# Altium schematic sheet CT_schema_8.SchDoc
size 278 x 170 mm
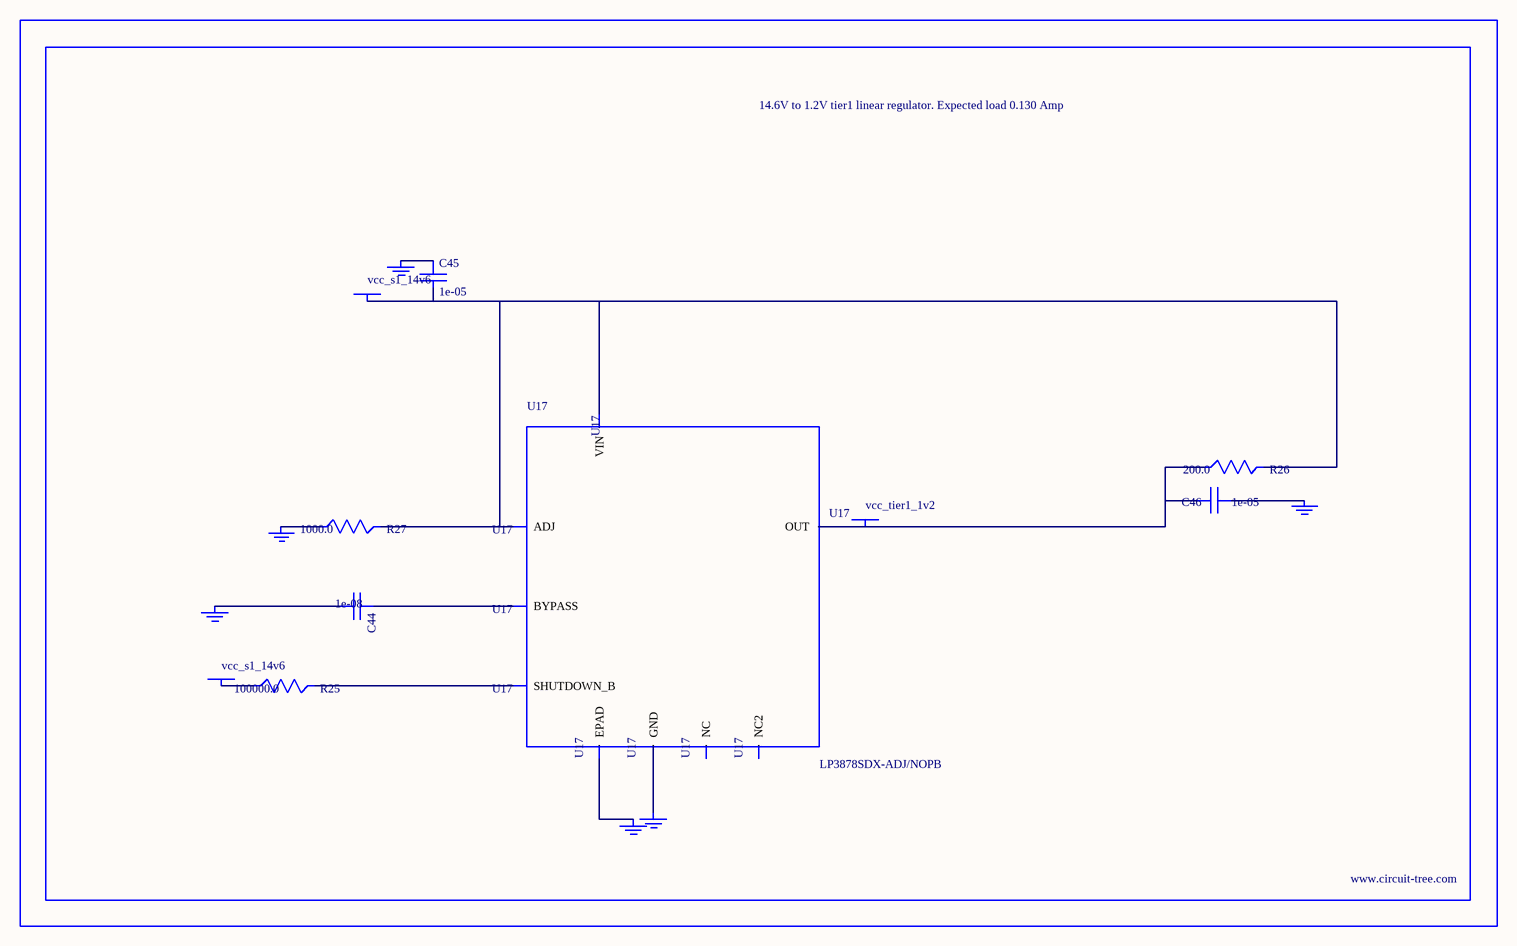
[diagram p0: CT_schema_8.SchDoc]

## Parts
BORDER7  (no value)
C44  1e-08  [C0402]
C45  1e-05  [C1210]
C46  1e-05  [C0805]
GND_INSTANCE_7_0  (no value)
GND_INSTANCE_7_1  (no value)
GND_INSTANCE_7_2  (no value)
GND_INSTANCE_7_3  (no value)
GND_INSTANCE_7_4  (no value)
GND_INSTANCE_7_5  (no value)
POWER_INSTANCE_7_0  vcc_s1_14v6
POWER_INSTANCE_7_1  vcc_s1_14v6
POWER_INSTANCE_7_2  vcc_tier1_1v2
R25  100000.0  [R0603]
R26  200.0  [R0603]
R27  1000.0  [R0603]
U17  LP3878SDX-ADJ/NOPB  [WSON-8]

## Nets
NetC44_1: C44.1 U17.1(BYPASS)
NetC44_2: C44.2 GND_INSTANCE_7_0.0(GND)
NetC45_1: C45.1 GND_INSTANCE_7_1.0(GND)
NetC45_2: C45.2 POWER_INSTANCE_7_0.0(PWR) R26.2 R27.2 U17.4(VIN) U17.6(ADJ)
NetC46_1: C46.1 GND_INSTANCE_7_2.0(GND)
NetC46_2: C46.2 POWER_INSTANCE_7_2.0(PWR) R26.1 U17.5(OUT)
NetGND_INSTANCE_7_3_0: GND_INSTANCE_7_3.0(GND) R27.1
NetGND_INSTANCE_7_4_0: GND_INSTANCE_7_4.0(GND) U17.PAD(EPAD)
NetGND_INSTANCE_7_5_0: GND_INSTANCE_7_5.0(GND) U17.3(GND)
NetPOWER_INSTANCE_7_1_0: POWER_INSTANCE_7_1.0(PWR) R25.1
NetR25_2: R25.2 U17.8(SHUTDOWN_B)

Not connected (* = marked no-connect by the designer): U17 2(NC) 7(NC2)

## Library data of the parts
BORDER7 = BORDER_PAGE7
C44 = C0402C103K3RAC
C45 = C1210C106K5PACTU
C46 = GRM219R60J106ME19D
GND_INSTANCE_7_0-GND_INSTANCE_7_5 = GND
POWER_INSTANCE_7_0-POWER_INSTANCE_7_2 = PWR
R25 = RC0603JR-07100KL
R26 = RC0603JR-07200RL
R27 = RC0603JR-071KL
